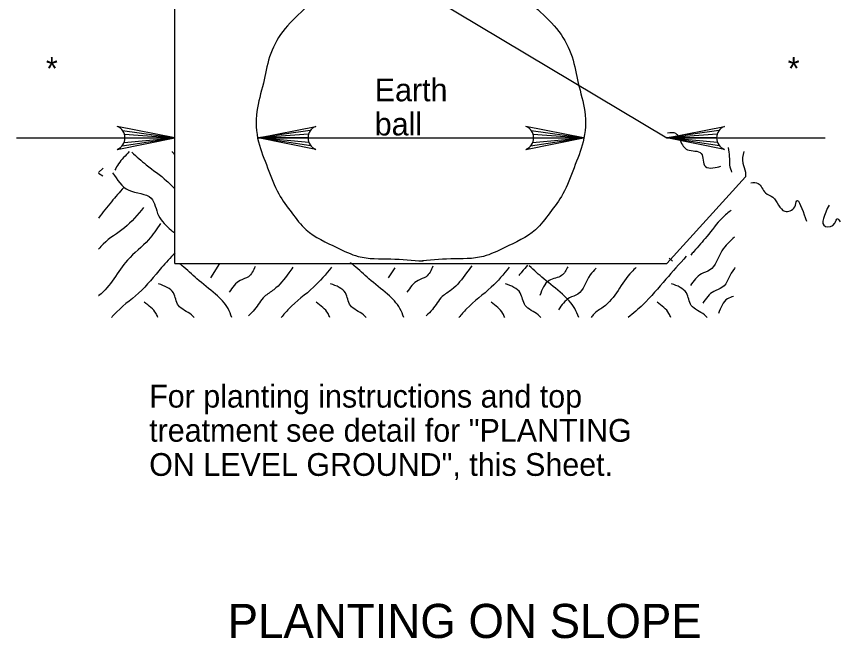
# Model space of a CAD drawing. Extents: x 3862.5 to 3891, y 3400.3 to 3419.7.
# Drawn here: x 3881.58 to 3886.65, y 3400.28 to 3404.1 of the extents above; entities that cross this region are included whole.
import ezdxf

# ---------------------------------------------------------------- set-up
doc = ezdxf.new("R2010")
doc.units = 0
doc.layers.add('DR_X_Trench_Drain', color=7, linetype='Continuous')
doc.layers.add('GT_X_Coal_Seam_1', color=7, linetype='Continuous')

msp = doc.modelspace()

# ---------------------------------------------------------------- linework, layer by layer
at = {"layer": 'DR_X_Trench_Drain'}
for p, q in [((3883.3973, 3404.6617), (3885.5806, 3403.3575)), ((3882.552, 3402.5849), (3882.552, 3404.5029)), ((3882.1122, 3403.1704), (3882.0832, 3403.1435)), ((3882.0832, 3403.1394), (3882.1091, 3403.1238)), ((3885.5806, 3402.5849), (3886.0636, 3403.118)), ((3885.6162, 3402.5997), (3885.5953, 3402.6183)), ((3882.552, 3402.5849), (3885.5806, 3402.5849)), ((3882.8276, 3402.5849), (3882.7721, 3402.496)), ((3883.9055, 3402.5588), (3883.8662, 3402.496))]:
    msp.add_line(p, q, dxfattribs=at)
for points in [[(3882.5038, 3404.742), (3882.844, 3404.7208), (3883.6368, 3404.6299), (3884.1822, 3404.5789), (3884.7276, 3404.6302), (3885.5788, 3404.707), (3886.0457, 3404.7397), (3886.3113, 3404.759), (3886.569, 3404.715), (3886.8043, 3404.6035), (3886.9533, 3404.4814), (3887.1626, 3404.3064), (3887.3698, 3403.9842), (3887.6515, 3403.6928), (3887.8125, 3403.4869), (3887.9775, 3403.2565), (3888.1183, 3403.0547), (3888.233, 3402.8444), (3888.4342, 3402.5937), (3888.5931, 3402.351), (3888.742, 3402.1205), (3888.901, 3401.8839), (3889.0438, 3401.7537), (3889.1746, 3401.5865), (3889.404, 3401.3174), (3889.6092, 3401.1035), (3889.7762, 3400.8609)], [(3883.8863, 3404.3895), (3883.7032, 3404.3398), (3883.516, 3404.2675), (3883.347, 3404.1462), (3883.2161, 3404.0107), (3883.1356, 3403.8549), (3883.0973, 3403.6933), (3883.0571, 3403.5193), (3883.0671, 3403.3333), (3883.1235, 3403.1739), (3883.1918, 3403.0127), (3883.2723, 3402.8964), (3883.3608, 3402.7925), (3883.55, 3402.6828), (3883.6808, 3402.6282), (3883.882, 3402.6125), (3884.0812, 3402.599)], [(3884.2462, 3404.3895), (3884.4293, 3404.3398), (3884.6166, 3404.2675), (3884.7856, 3404.1462), (3884.9165, 3404.0107), (3884.997, 3403.8549), (3885.0352, 3403.6933), (3885.0755, 3403.5193), (3885.0655, 3403.3333), (3885.0091, 3403.1739), (3884.9407, 3403.0127), (3884.8602, 3402.8964), (3884.7717, 3402.7925), (3884.5826, 3402.6828), (3884.4517, 3402.6282), (3884.2505, 3402.6125), (3884.0513, 3402.599)], [(3885.5847, 3403.3882), (3885.633, 3403.3863), (3885.6631, 3403.3414), (3885.7075, 3403.2844), (3885.792, 3403.2622), (3885.8181, 3403.1805), (3885.8643, 3403.1725), (3885.9127, 3403.1829)], [(3882.2723, 3403.2728), (3882.206, 3403.1977), (3882.1831, 3403.1594)], [(3882.2882, 3403.2685), (3882.3761, 3403.1922), (3882.5021, 3403.0929), (3882.552, 3403.043)], [(3882.5361, 3403.2728), (3882.5365, 3403.2724), (3882.552, 3403.2522)], [(3885.957, 3403.2977), (3885.965, 3403.2424), (3885.967, 3403.1893), (3885.9791, 3403.1464)], [(3886.0536, 3403.2734), (3886.0475, 3403.2019), (3886.0636, 3403.1467), (3886.0636, 3403.118)], [(3882.1698, 3403.1427), (3882.2691, 3403.0357), (3882.4066, 3402.986), (3882.4525, 3402.8792), (3882.5288, 3402.7913), (3882.552, 3402.772)], [(3886.0978, 3403.0814), (3886.1421, 3403.0775), (3886.1883, 3403.0184), (3886.2326, 3402.992), (3886.3071, 3402.9064), (3886.3675, 3402.9332), (3886.3795, 3402.97), (3886.4318, 3402.868), (3886.4398, 3402.8455)], [(3882.2382, 3403.052), (3882.1618, 3402.9642), (3882.0832, 3402.8644)], [(3882.3605, 3402.9299), (3882.2421, 3402.8038), (3882.1122, 3402.7045), (3882.0832, 3402.6724)], [(3885.9773, 3402.9133), (3885.9221, 3402.8653), (3885.8266, 3402.7508), (3885.7465, 3402.659), (3885.7273, 3402.6362)], [(3886.5787, 3402.9443), (3886.5566, 3402.8133), (3886.615, 3402.8319), (3886.6291, 3402.8607), (3886.6472, 3402.8403)], [(3882.4635, 3402.8305), (3882.391, 3402.7313), (3882.2611, 3402.6053), (3882.1771, 3402.4907), (3882.0855, 3402.3877), (3882.0832, 3402.3859)], [(3885.9968, 3402.7475), (3885.9198, 3402.6624), (3885.8435, 3402.544), (3885.7938, 3402.5212), (3885.7251, 3402.4485)], [(3882.552, 3402.65), (3882.4711, 3402.5594), (3882.3298, 3402.4029), (3882.1771, 3402.2693), (3882.1625, 3402.2527)], [(3885.7001, 3402.629), (3885.5741, 3402.4877), (3885.4328, 3402.3312), (3885.3431, 3402.2527)], [(3882.9033, 3402.2527), (3882.8797, 3402.3078), (3882.8033, 3402.3955), (3882.6888, 3402.491), (3882.5972, 3402.5713), (3882.5808, 3402.5849)], [(3883.0458, 3402.5668), (3883.0051, 3402.5037), (3882.9555, 3402.4808), (3882.8867, 3402.4082)], [(3883.2786, 3402.5612), (3883.2532, 3402.5265), (3883.1616, 3402.4235), (3883.1043, 3402.3815), (3883.0432, 3402.3013), (3883.0051, 3402.263)], [(3883.5165, 3402.5613), (3883.406, 3402.4388), (3883.2532, 3402.3052), (3883.207, 3402.2527)], [(3883.9616, 3402.2527), (3883.938, 3402.3078), (3883.8616, 3402.3955), (3883.7471, 3402.491), (3883.6555, 3402.5713), (3883.6326, 3402.5903)], [(3884.1405, 3402.5678), (3884.0991, 3402.5037), (3884.0495, 3402.4808), (3883.9808, 3402.4082)], [(3884.3796, 3402.5704), (3884.3473, 3402.5265), (3884.2557, 3402.4235), (3884.1985, 3402.3815), (3884.1373, 3402.3013), (3884.0991, 3402.263)], [(3884.6106, 3402.5613), (3884.5001, 3402.4388), (3884.3473, 3402.3052), (3884.3011, 3402.2527)], [(3884.7238, 3402.5743), (3884.6882, 3402.5335), (3884.6691, 3402.5107)], [(3885.0378, 3402.2527), (3885.0142, 3402.3078), (3884.9378, 3402.3955), (3884.8232, 3402.491), (3884.7337, 3402.5694)], [(3884.9715, 3402.5652), (3884.9326, 3402.5107), (3884.8562, 3402.48), (3884.7988, 3402.3884)], [(3885.1461, 3402.5564), (3885.1082, 3402.5144), (3885.0318, 3402.396), (3884.9822, 3402.3732), (3884.9135, 3402.3005)], [(3885.3917, 3402.5604), (3885.3641, 3402.5335), (3885.2801, 3402.4189), (3885.1885, 3402.3159), (3885.1311, 3402.2739), (3885.115, 3402.2527)], [(3886.0005, 3402.5597), (3885.9961, 3402.5548), (3885.9197, 3402.4364), (3885.8701, 3402.4135), (3885.8013, 3402.3409)], [(3882.6715, 3402.2527), (3882.6545, 3402.2695), (3882.5743, 3402.3269), (3882.5437, 3402.4033), (3882.4521, 3402.4605)], [(3883.7297, 3402.2527), (3883.7127, 3402.2695), (3883.6326, 3402.3269), (3883.602, 3402.4033), (3883.5103, 3402.4605)], [(3884.8058, 3402.2527), (3884.789, 3402.2695), (3884.7087, 3402.3269), (3884.6782, 3402.4033), (3884.5865, 3402.4605)], [(3885.8282, 3402.2527), (3885.8112, 3402.2695), (3885.7311, 3402.3269), (3885.7005, 3402.4033), (3885.6088, 3402.4605)], [(3885.99, 3402.382), (3885.9547, 3402.3679), (3885.8975, 3402.2763)], [(3882.4482, 3402.2527), (3882.4368, 3402.2772), (3882.3643, 3402.3459)], [(3883.5065, 3402.2527), (3883.4951, 3402.2772), (3883.4225, 3402.3459)], [(3884.5826, 3402.2527), (3884.5712, 3402.2772), (3884.4987, 3402.3459)], [(3885.605, 3402.2527), (3885.5936, 3402.2772), (3885.5211, 3402.3459)]]:
    msp.add_spline(points, degree=3, dxfattribs=at)
at = {"layer": 'GT_X_Coal_Seam_1'}
for p, q in [((3882.2313, 3403.4024), (3882.552, 3403.3575)), ((3882.2422, 3403.3802), (3882.552, 3403.3575)), ((3883.3863, 3403.4024), (3883.0658, 3403.3575)), ((3883.3756, 3403.3802), (3883.0658, 3403.3575)), ((3884.7461, 3403.4024), (3885.0667, 3403.3575)), ((3884.757, 3403.3802), (3885.0667, 3403.3575)), ((3885.9012, 3403.4024), (3885.5806, 3403.3575)), ((3885.8903, 3403.3802), (3885.5806, 3403.3575)), ((3881.5778, 3403.3575), (3882.552, 3403.3575)), ((3882.2276, 3403.3079), (3882.552, 3403.3575)), ((3882.2398, 3403.3287), (3882.552, 3403.3575)), ((3882.2455, 3403.3575), (3882.552, 3403.3575)), ((3883.0658, 3403.3575), (3883.7693, 3403.3575)), ((3883.3722, 3403.3575), (3883.0658, 3403.3575)), ((3883.3778, 3403.3287), (3883.0658, 3403.3575)), ((3883.3902, 3403.3079), (3883.0658, 3403.3575)), ((3883.7693, 3403.3575), (3885.0667, 3403.3575)), ((3884.2441, 3403.3575), (3885.0667, 3403.3575)), ((3884.7423, 3403.3079), (3885.0667, 3403.3575)), ((3884.7546, 3403.3287), (3885.0667, 3403.3575)), ((3884.7603, 3403.3575), (3885.0667, 3403.3575)), ((3885.5806, 3403.3575), (3886.5547, 3403.3575)), ((3885.8871, 3403.3575), (3885.5806, 3403.3575)), ((3885.8927, 3403.3287), (3885.5806, 3403.3575)), ((3885.905, 3403.3079), (3885.5806, 3403.3575))]:
    msp.add_line(p, q, dxfattribs=at)
for points in [[(3882.1978, 3403.2867), (3882.552, 3403.3575), (3882.1978, 3403.4283)], [(3883.42, 3403.2867), (3883.0658, 3403.3575), (3883.42, 3403.4283)], [(3884.7126, 3403.2867), (3885.0667, 3403.3575), (3884.7126, 3403.4283)], [(3885.9347, 3403.2867), (3885.5806, 3403.3575), (3885.9347, 3403.4283)]]:
    msp.add_lwpolyline(points, dxfattribs=at)
for centre, start, end in [((3882.1692, 3403.3576), 292.0861, 67.9122), ((3883.4485, 3403.3576), 112.0878, 247.9139), ((3884.684, 3403.3576), 292.0861, 67.9122), ((3885.9633, 3403.3576), 112.0878, 247.9139)]:
    msp.add_arc(centre, 0.0764, start, end, dxfattribs=at)

# ---------------------------------------------------------------- texts
for p in [(3881.7611, 3403.7133), (3886.3264, 3403.7133)]:
    msp.add_text('*', height=0.14, rotation=1, dxfattribs=at).set_placement(p)
for s, height, p in [('Earth', 0.14, (3883.7829, 3403.5824)), ('ball', 0.14, (3883.7829, 3403.3724)), ('For planting instructions and top', 0.14, (3882.3946, 3401.6985)), ('treatment see detail for "PLANTING', 0.14, (3882.3946, 3401.4885)), ('ON LEVEL GROUND", this Sheet.', 0.14, (3882.3946, 3401.2785)), ('PLANTING ON SLOPE', 0.21, (3882.8772, 3400.2811))]:
    msp.add_text(s, height=height, dxfattribs=at).set_placement(p)

doc.saveas('drawing.dxf')
